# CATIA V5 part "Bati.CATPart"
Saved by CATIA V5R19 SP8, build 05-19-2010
Part number: Bati
Bounding box of the stored display mesh (mm): x -20 to 7, y -42.969 to 42.969, z -108.481 to 42.808
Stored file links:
  C:\Users\ThinkMotion\Desktop\EU_thinkMotion\iao\IAO_MMS_Groupe3\pmayet\pmayet_avant_optimisation\pmayet_avant_optimisation\Bati.CATPart
  C:\Users\ThinkMotion\Desktop\EU_thinkMotion\iao\IAO_MMS_Groupe3\pmayet\pmayet_avant_optimisation\pmayet_avant_optimisation\pmayet.CATProduct
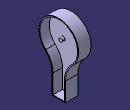
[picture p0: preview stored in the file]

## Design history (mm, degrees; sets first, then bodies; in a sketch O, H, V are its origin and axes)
Parameters
  Rayon_bati = 43 mm
  Hauteur_pour_coulisseau = 68 mm
  Largeur_pour_coulisseau = 29 mm
  Epaisseur_bati = 20 mm
  Rayon_arbre_bati = 4 mm
  Epaisseur_tour_bati = 2 mm
  Rayon_aiguille = 1.25 mm
  `Epaisseur_bielle ` = 5 mm
Set1
  Plane1: linked copy from another document
  Point1 "PointA": linked copy from another document
  Point2 "Point_origine_aiguille": linked copy from another document
Body1 (main body)
  Sketch1 on Plane1, origin (0, 0, 0), H (0, 1, 0), V (0, 0, 1)
    arc A1 centre (0, 0) radius 43 from (30.1, -30.7081) to (-30.1, -30.7081) ccw
    point P1 (0, 0)
    point P2 (14.5, -40.4815)
    point P3 (-14.5, -40.4815)
    reference projected point E1 (0, 0) from Point1
    point P4 (-14.5, -40.4815)
    line L1 (14.5, -67.8436) -> (14.5, -108.4815)
    line L2 (14.5, -108.4815) -> (-14.5, -108.4815)
    line L3 (-14.5, -108.4815) -> (-14.5, -67.8436)
    point P5 (14.5, -40.4815)
    point P6 (14.5, -108.4815)
    point P7 (-14.5, -108.4815)
    reference projected point E2 (0, 0) from Point1
    reference projected point E3 (0, 0) from Point1
    arc A2 centre (-66.5, -67.8436) radius 52 from (-30.1, -30.7081) to (-14.5, -67.8436) cw
    arc A3 centre (66.5, -67.8436) radius 52 from (30.1, -30.7081) to (14.5, -67.8436) ccw
    radius A1 = 43 {= Rayon_bati}
    distance E2 L1 = 14.5 {= Largeur_pour_coulisseau /2}
    distance E3 L3 = 14.5 {= Largeur_pour_coulisseau /2}
    distance P5 P2 = 0
    distance P7 P4 = 68 {= Hauteur_pour_coulisseau}
    radius A2 = 52
    distance P5 P6 = 68 {= Hauteur_pour_coulisseau}
    radius A3 = 52
    coincidence: P1 E1, P3 P4, A1 P3, L3 P4, A1 P2, L1 P5
    horizontal: L2 H
    vertical: L1 V, L3 V
    tangency: A2 A1, A2 L3, A3 A1, A3 L1
  Pad1: profile Sketch1, direction (-1, 0, 0), length 20 {= Epaisseur_bati}
  Sketch2 on Plane1, origin (0, 0, 0), H (0, 1, 0), V (0, 0, 1)
    arc A1 centre (0, 0) radius 41 from (28.1593, -29.8002) to (-28.1593, -29.8002) ccw
    point P1 (0, 0)
    point P2 (12.5, -39.048)
    point P3 (-12.5, -39.048)
    reference projected point E1 (0, 0) from Point1
    point P4 (-12.5, -39.048)
    line L1 (12.5, -66.1419) -> (12.5, -107.048)
    line L2 (12.5, -107.048) -> (-12.5, -107.048)
    line L3 (-12.5, -107.048) -> (-12.5, -66.1419)
    point P5 (12.5, -39.048)
    point P6 (12.5, -107.048)
    point P7 (-12.5, -107.048)
    reference projected point E2 (0, 0) from Point1
    reference projected point E3 (0, 0) from Point1
    arc A2 centre (62.5, -66.1419) radius 50 from (28.1593, -29.8002) to (12.5, -66.1419) ccw
    arc A3 centre (-62.5, -66.1419) radius 50 from (-28.1593, -29.8002) to (-12.5, -66.1419) cw
    radius A1 = 41 {= Rayon_bati -Epaisseur_tour_bati}
    distance E2 L1 = 12.5 {= Largeur_pour_coulisseau /2 - Epaisseur_tour_bati}
    distance E3 L3 = 12.5 {= Largeur_pour_coulisseau /2 - Epaisseur_tour_bati}
    distance P5 P2 = 0
    distance P5 P6 = 68 {= Hauteur_pour_coulisseau}
    radius A2 = 50
    distance P7 P4 = 68 {= Hauteur_pour_coulisseau}
    radius A3 = 50
    coincidence: P1 E1, P3 P4, A1 P2, L1 P5, A1 P3, L3 P4
    horizontal: L2 H
    vertical: L1 V, L3 V
    tangency: A2 L1, A2 A1, A3 A1, A3 L3
  Pocket1: profile Sketch2, direction (-1, 0, 0), length 13.3333 {= Epaisseur_bati *2/3}, mirrored extent
  Sketch3 on face of Pad1 from Sketch1.L2, origin (0, 0, -108.4815), H (1, 0, 0), V (0, -1, 0)
    circle A1 centre (-6, -6.5) radius 1.875
    point P1 (-6, -6.5)
    reference projected point E1 (-6, -6.5) from Point2
    distance A1 P1 = 1.875 {= Rayon_aiguille *1.5}
    coincidence: E1 P1
  Pocket2: profile Sketch3, direction (0, 0, 1), length 2 {= Epaisseur_tour_bati}
  Sketch4 on start face of Pad1, origin (0, 0, 0), H (0, 1, 0), V (0, 0, 1)
    arc A1 centre (0, 0) radius 43 from (30.1, -30.7081) to (-30.1, -30.7081) ccw
    point P1 (0, 0)
    point P2 (14.5, -40.4815)
    point P3 (-14.5, -40.4815)
    reference projected point E1 (0, 0) from Point1
    arc A2 centre (0, 0) radius 41 from (28.1593, -29.8002) to (-28.1593, -29.8002) ccw
    point P4 (0, 0)
    point P5 (12.5, -39.048)
    point P6 (-12.5, -39.048)
    reference projected point E2 (0, 0) from Point1
    point P7 (-14.5, -40.4815)
    line L1 (14.5, -67.8436) -> (14.5, -108.4815)
    line L2 (14.5, -108.4815) -> (-14.5, -108.4815)
    line L3 (-14.5, -108.4815) -> (-14.5, -67.8436)
    point P8 (14.5, -40.4815)
    reference projected line E3 (-14.5, -108.4815) -> (14.5, -108.4815) from edge [face of Pad1 from Sketch1.L2 | start face of Pad1]
    reference projected line E4 (14.5, -108.4815) -> (14.5, -51.6212) from edge [face of Pad1 from Sketch1.L1 | start face of Pad1]
    reference projected line E5 (-14.5, -51.6212) -> (-14.5, -108.4815) from edge [face of Pad1 from Sketch1.L3 | start face of Pad1]
    arc A3 centre (66.5, -67.8436) radius 52 from (30.1, -30.7081) to (14.5, -67.8436) ccw
    arc A4 centre (-66.5, -67.8436) radius 52 from (-30.1, -30.7081) to (-14.5, -67.8436) cw
    point P17 (-12.5, -39.048)
    line L4 (12.5, -66.1419) -> (12.5, -107.048)
    line L5 (12.5, -107.048) -> (-12.5, -107.048)
    line L6 (-12.5, -107.048) -> (-12.5, -66.1419)
    point P18 (12.5, -39.048)
    reference projected line E6 (12.5, -107.048) -> (-12.5, -107.048) from edge [face of Pocket1 from Sketch2.L2 | start face of Pad1]
    reference projected line E7 (12.5, -107.048) -> (12.5, -49.3634) from edge [start face of Pad1 | face of Pocket1 from Sketch2.L1]
    reference projected line E8 (-12.5, -49.3634) -> (-12.5, -107.048) from edge [start face of Pad1 | face of Pocket1 from Sketch2.L3]
    arc A5 centre (-62.5, -66.1419) radius 50 from (-28.1593, -29.8002) to (-12.5, -66.1419) cw
    arc A6 centre (62.5, -66.1419) radius 50 from (28.1593, -29.8002) to (12.5, -66.1419) ccw
    radius A1 = 43 {= Rayon_bati}
    radius A2 = 41 {= Rayon_bati -Epaisseur_tour_bati}
    radius A3 = 52
    radius A4 = 52
    radius A5 = 50
    radius A6 = 50
    coincidence: E1 P1, E2 P4, L2 E3, E4 L1, E5 L3, P3 P7, P8 P2, A1 P2, L1 P8, A1 P3, L3 P7, L5 E6, E7 L4, E8 L6, P5 P18, P6 P17, A2 P6, L6 P17, A2 P5, L4 P18
    horizontal: L2 H, L5 H
    vertical: L1 V, L3 V, L4 V, L6 V
    tangency: A3 L1, A3 A1, A4 A1, A4 L3, A5 A2, A5 L6, A6 A2, A6 L4
  Pad2: profile Sketch4, direction (1, 0, 0), length 7 {= `Epaisseur_bielle ` + 2mm}
  Sketch5 on Plane1, origin (0, 0, 0), H (0, 1, 0), V (0, 0, 1)
    circle A1 centre (0, 0) radius 4
    point P1 (0, 0)
    reference projected point E1 (0, 0) from Point1
    distance A1 P1 = 4 {= Rayon_arbre_bati}
    coincidence: E1 P1
  Pad3: profile Sketch5, direction (1, 0, 0), length 3 {= Epaisseur_bati /4 -2mm}, mirrored extent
